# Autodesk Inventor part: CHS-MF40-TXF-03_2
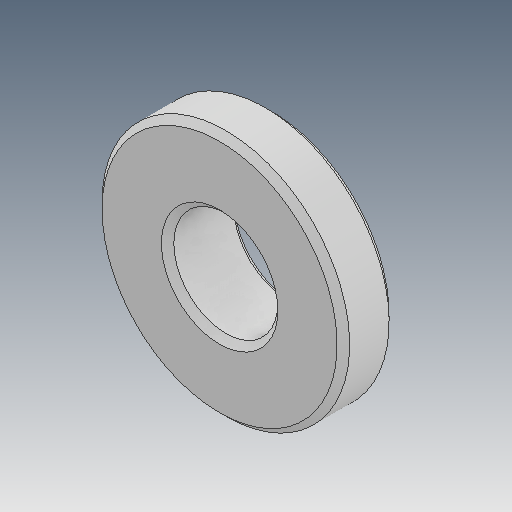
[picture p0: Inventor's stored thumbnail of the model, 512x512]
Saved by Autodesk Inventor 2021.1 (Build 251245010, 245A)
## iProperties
Created: 2019-05
Part Number: CHS-MF40-TXF-03_2
Material: Ogólny
Document SubType Name: Modeling
Designer: user
Density: 1 g/cm^3
Appearance: Domyślna
Author: user
Revision Number: ÈÎºÎ
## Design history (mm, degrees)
feature "ÊäÈë1"
node "Bryła1"
